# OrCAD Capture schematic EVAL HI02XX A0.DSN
size A; title: EVAL HI02; rev: A0; note: 1
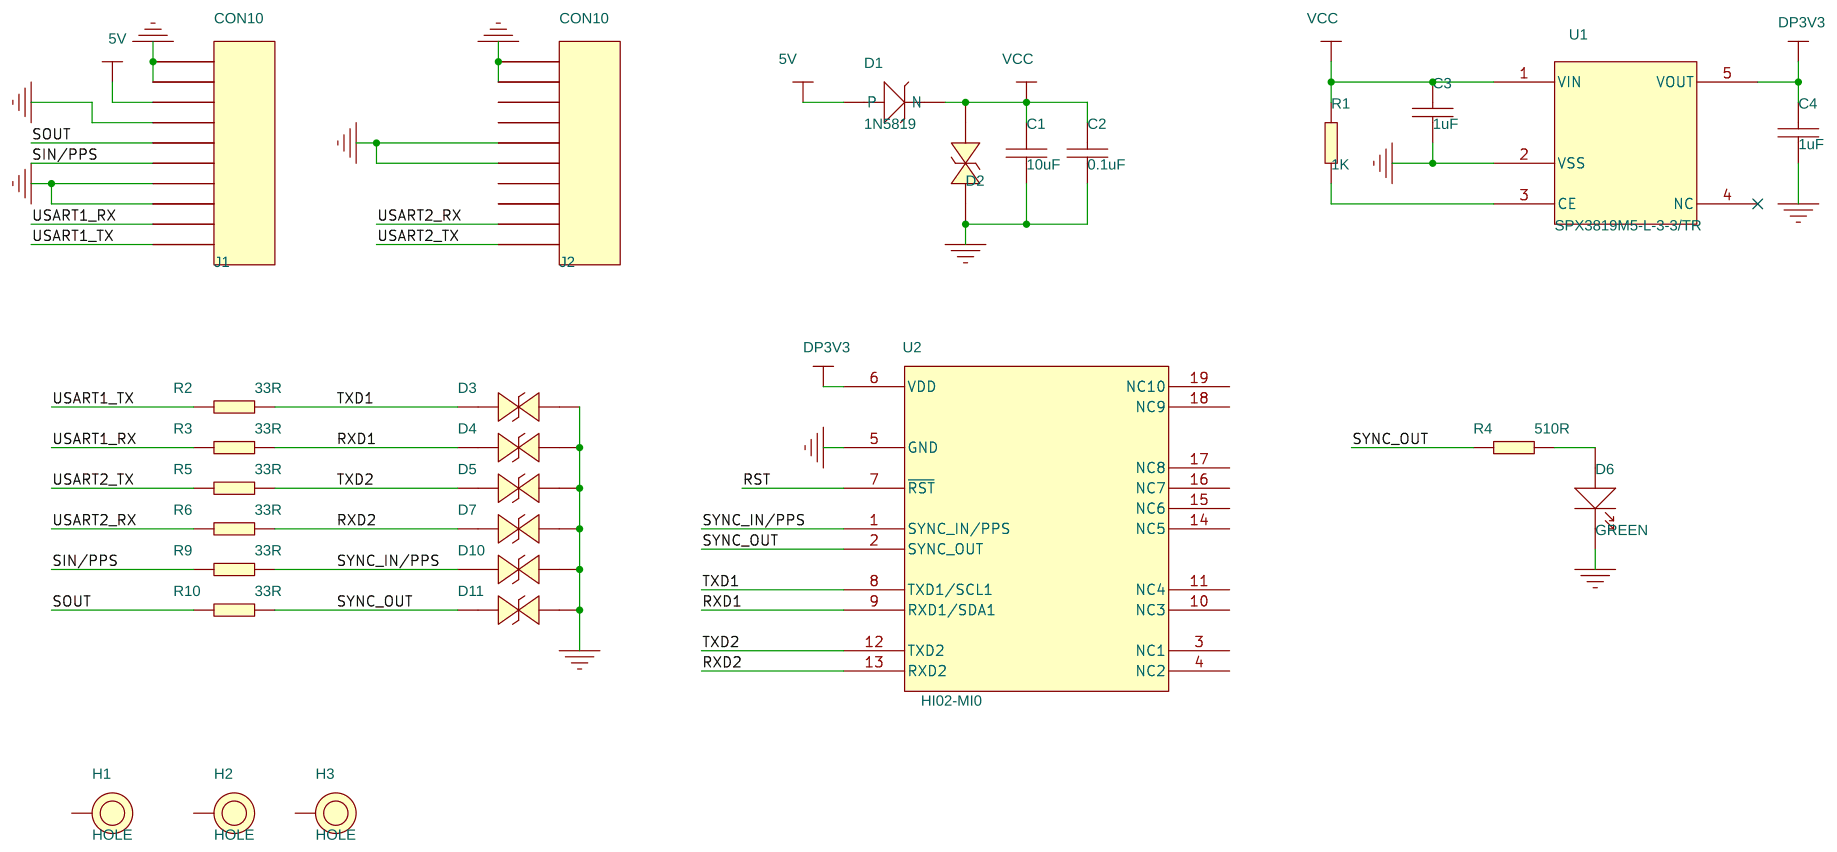
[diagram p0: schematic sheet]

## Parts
C1  10uF  [C0603]
C2  0.1uF  [C0402]
C3  1uF  [C0402]
C4  1uF  [C0402]
D1  1N5819  [SOD123FL]
D2  SDD32A05L01  [SOD123FL]
D3  SBD52C05L01  [SOD-523]
D4  SBD52C05L01  [SOD-523]
D5  SBD52C05L01  [SOD-523]
D6  GREEN  [LED0402]
D7  SBD52C05L01  [SOD-523]
D10  SBD52C05L01  [SOD-523]
D11  SBD52C05L01  [SOD-523]
H1  HOLE  [HOLE-2-MM]
H2  HOLE  [HOLE-2-MM]
H3  HOLE  [HOLE-2-MM]
J1  CON10  [5015680807_1]
J2  CON10  [5015680807_1]
R1  1K  [R0402]
R2  33R  [R0402]
R3  33R  [R0402]
R4  510R  [R0402]
R5  33R  [R0402]
R6  33R  [R0402]
R9  33R  [R0402]
R10  33R  [R0402]
U1  SPX3819M5-L-3-3/TR  [SOT23-5-0_95]
U2  HI02-MI0  [HI02_HI05]

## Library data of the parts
C1-C4 = Capacity_Nonpolarity
D1 = diode
D2-D5 D7 D10 D11 = DIODE_BI-DIR_TRIG
D6 = LED
H1-H3 = HOLE
J1 J2 = CON10
R1-R6 R9 R10 = Res
U1 = XC6210
U2 = HI02-MI0

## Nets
5V: D1.1(P) J1.8
GND: C1.1 C2.1 C3.2 C4.1 D2.1 D3.1 D4.1 D5.1 D6.2(-) D7.1 D10.1 D11.1 J1.3 J1.4 J1.7 J1.9 J1.10 J2.5 J2.6 J2.9 J2.10 U1.2(VSS) U2.5(GND)
VCC: C1.2 C2.2 C3.1 D1.2(N) D2.2 R1.2 U1.1(VIN)
DP3V3: C4.2 U1.5(VOUT) U2.6(VDD)
RST: U2.7(~{RST})
RXD1: D4.2 R3.1 U2.9(RXD1/SDA1)
RXD2: D7.2 R6.1 U2.13(RXD2)
SIN/PPS: J1.5 R9.2
SOUT: J1.6 R10.2
SYNC_IN/PPS: D10.2 R9.1 U2.1(SYNC_IN/PPS)
SYNC_OUT: D11.2 R4.1 R10.1 U2.2(SYNC_OUT)
TXD1: D3.2 R2.1 U2.8(TXD1/SCL1)
TXD2: D5.2 R5.1 U2.12(TXD2)
USART1_RX: J1.2 R3.2
USART1_TX: J1.1 R2.2
USART2_RX: J2.2 R6.2
USART2_TX: J2.1 R5.2
N2198535: D6.1(+) R4.2
N2224750: R1.1 U1.3(CE)

Not connected (* = marked no-connect by the designer): H1 1; H2 1; H3 1; J2 3 4 7 8; U1 4(NC)*; U2 3(NC1) 4(NC2) 10(NC3) 11(NC4) 14(NC5) 15(NC6) 16(NC7) 17(NC8) 18(NC9) 19(NC10)
